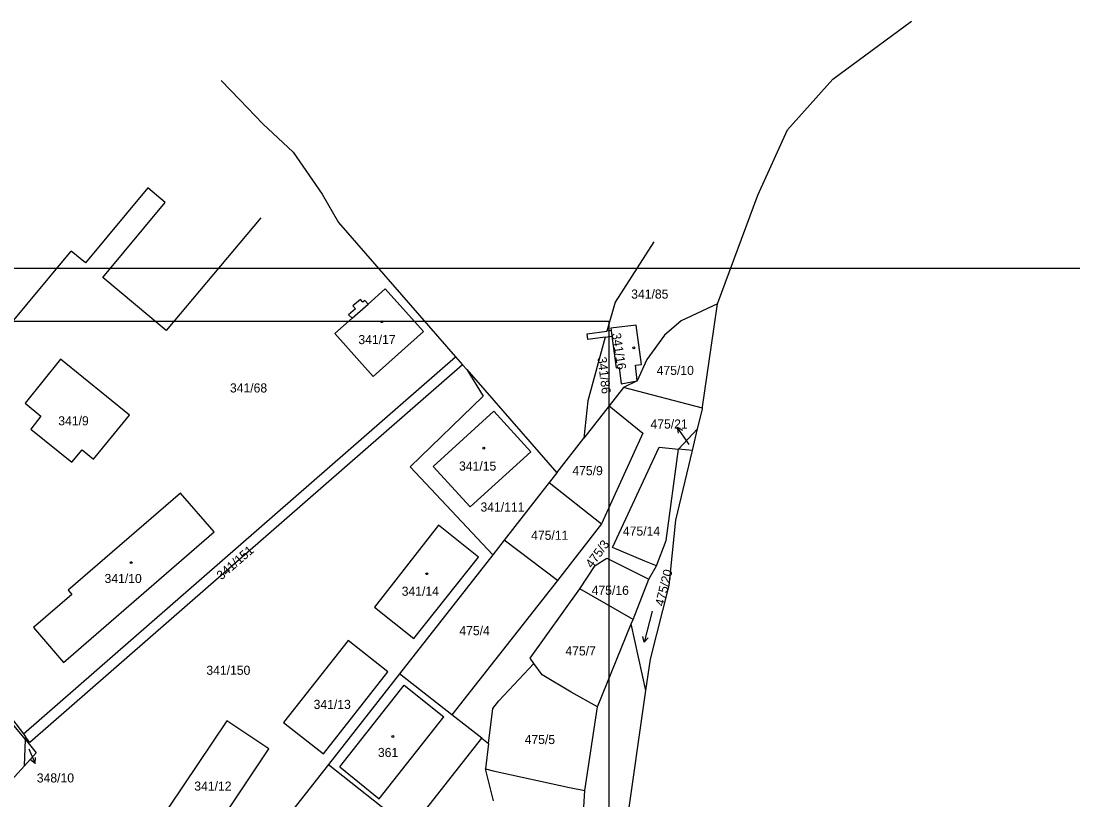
# Model space of a CAD drawing. Extents: x -558500 to -557517, y -1073973 to -1073051.
# Drawn here: x -557909.9 to -557713.2, y -1073289.5 to -1073143.9 of the extents above; entities that cross this region are included whole.
import ezdxf

# ---------------------------------------------------------------- set-up
doc = ezdxf.new("R2010")
doc.units = 0
for name, color, linetype in [('Default', 7, 'Continuous'), ('Hranice parcel', 7, 'Continuous'), ('Parcelní čísla', 7, 'Continuous'), ('Pop  PČ popisy', 7, 'Continuous'), ('Vnitřní kresba', 7, 'Continuous'), ('Vrstva 1', 7, 'Continuous'), ('Značky budov', 7, 'Continuous'), ('Značky kultur', 7, 'Continuous')]:
    doc.layers.add(name, color=color, linetype=linetype)

msp = doc.modelspace()

# ---------------------------------------------------------------- linework, layer by layer
at = {"layer": 'Default'}
msp.add_lwpolyline([(-557909.21, -1073700), (-558500, -1073700), (-558500, -1073200), (-557800, -1073200), (-557800, -1073567.6)], dxfattribs=at)
at = {"layer": 'Hranice parcel'}
for p, q in [((-557780.35, -1073201.52), (-557779.66, -1073196.74)), ((-557782.46, -1073216.02), (-557780.35, -1073201.52)), ((-557909.46, -1073277.19), (-557828.67, -1073206.65)), ((-557828.67, -1073206.65), (-557827.35, -1073208.16)), ((-557827.35, -1073208.16), (-557826.56, -1073209.07)), ((-557826.56, -1073209.07), (-557809.74, -1073228.36)), ((-557794.69, -1073211.15), (-557797.26, -1073212.4)), ((-557797.26, -1073212.4), (-557799.96, -1073215.86)), ((-557782.49, -1073216.26), (-557797.26, -1073212.4)), ((-557799.96, -1073215.86), (-557804.68, -1073221.89)), ((-557782.49, -1073216.26), (-557782.46, -1073216.02)), ((-557786.97, -1073223.95), (-557783.4, -1073220.15)), ((-557784.37, -1073224.22), (-557783.4, -1073220.15)), ((-557809.74, -1073228.36), (-557804.68, -1073221.89)), ((-557784.37, -1073224.22), (-557786.97, -1073223.95)), ((-557809.74, -1073228.36), (-557811.18, -1073230.2)), ((-557811.18, -1073230.2), (-557819.59, -1073240.96)), ((-557811.18, -1073230.2), (-557801.34, -1073237.87)), ((-557801.34, -1073237.87), (-557809.56, -1073248.5)), ((-557819.59, -1073240.96), (-557821.71, -1073243.68)), ((-557809.56, -1073248.5), (-557819.59, -1073240.96)), ((-557821.71, -1073243.68), (-557839.11, -1073265.95)), ((-557792.5, -1073248.24), (-557791.11, -1073245.75)), ((-557795.47, -1073255.77), (-557792.5, -1073248.24)), ((-557795.47, -1073255.77), (-557805.42, -1073250.06)), ((-557909.08, -1073278.25), (-557930.32, -1073252.64)), ((-557795.8, -1073256.6), (-557795.47, -1073255.77)), ((-557802.11, -1073272.13), (-557795.8, -1073256.6)), ((-557793.06, -1073269.04), (-557795.8, -1073256.6)), ((-557839.11, -1073265.95), (-557852.38, -1073282.88)), ((-557829.36, -1073273.59), (-557839.11, -1073265.95)), ((-557796.66, -1073294.23), (-557793.06, -1073269.04)), ((-557804.5, -1073287.75), (-557802.11, -1073272.13)), ((-557823.76, -1073277.98), (-557829.36, -1073273.59)), ((-557909.46, -1073277.19), (-557909.06, -1073277.71)), ((-557909.06, -1073277.71), (-557909.08, -1073278.25)), ((-557837.1, -1073294.96), (-557823.76, -1073277.98)), ((-557823.76, -1073277.98), (-557822.5, -1073278.97)), ((-557909.23, -1073283.14), (-557909.08, -1073278.25)), ((-557822.5, -1073278.97), (-557823.08, -1073283.72)), ((-557912.91, -1073287.22), (-557909.23, -1073283.14)), ((-557852.38, -1073282.88), (-557892.99, -1073334.25)), ((-557852.38, -1073282.88), (-557837.1, -1073294.96)), ((-557821.55, -1073289.72), (-557823.08, -1073283.72)), ((-557805.19, -1073300.2), (-557804.5, -1073287.75))]:
    msp.add_line(p, q, dxfattribs=at)
for points in [[(-557779.66, -1073196.74), (-557772.11, -1073176.43), (-557766.56, -1073164.21), (-557758.13, -1073154.77), (-557743.42, -1073143.89)], [(-557872.45, -1073154.98), (-557868.98, -1073158.62), (-557864.71, -1073163.09), (-557859, -1073168.41), (-557853.62, -1073176.23), (-557850.51, -1073181.56), (-557828.67, -1073206.65)], [(-557886.21, -1073175.05), (-557897.85, -1073189.08), (-557900.5, -1073186.91)], [(-557865.08, -1073180.66), (-557882.73, -1073201.74), (-557894.59, -1073191.83), (-557882.93, -1073177.84), (-557886.21, -1073175.05)], [(-557933.22, -1073178.38), (-557938.16, -1073184.28), (-557924.03, -1073196.06), (-557926.52, -1073199.04), (-557917.14, -1073206.89), (-557900.5, -1073186.91)], [(-557791.57, -1073185.2), (-557798.84, -1073196.43), (-557800.39, -1073201.86)], [(-557845.64, -1073196.14), (-557845.97, -1073196.44), (-557846.43, -1073195.93), (-557847.88, -1073197.13), (-557847.39, -1073197.71), (-557848.66, -1073198.84), (-557848, -1073199.43), (-557851.22, -1073202.29), (-557844.06, -1073210.35), (-557834.66, -1073201.96), (-557841.8, -1073193.95), (-557845.02, -1073196.82), (-557845.64, -1073196.14)], [(-557779.66, -1073196.74), (-557786.44, -1073199.97), (-557789.57, -1073202.65), (-557792.87, -1073207.17), (-557794.69, -1073211.15)], [(-557794.69, -1073211.15), (-557795, -1073208.24), (-557793.89, -1073208.1), (-557794.86, -1073200.76), (-557799.62, -1073201.3), (-557799.56, -1073201.75), (-557800.39, -1073201.86)], [(-557800.69, -1073202.99), (-557803.91, -1073214.91), (-557804.68, -1073221.89)], [(-557800.69, -1073202.99), (-557803.9, -1073203.42), (-557804.04, -1073202.35), (-557800.39, -1073201.86)], [(-557800.69, -1073202.99), (-557799.42, -1073202.82), (-557798.62, -1073208.73), (-557798.08, -1073208.66), (-557797.7, -1073211.74), (-557794.69, -1073211.15)], [(-557906.17, -1073217.76), (-557908.09, -1073220.19), (-557900.4, -1073226.4), (-557898.47, -1073224.04), (-557896.35, -1073225.84), (-557889.61, -1073217.61), (-557902.52, -1073207.11), (-557909.1, -1073215.34), (-557906.17, -1073217.76)], [(-557827.35, -1073208.16), (-557908.24, -1073278.78), (-557909.06, -1073277.71)], [(-557826.56, -1073209.07), (-557823.48, -1073214.05), (-557837.12, -1073227.22), (-557821.71, -1073243.68)], [(-557821.48, -1073216.83), (-557832.85, -1073227.17), (-557825.95, -1073234.71), (-557814.6, -1073224.41), (-557821.48, -1073216.83)], [(-557799.96, -1073215.86), (-557793.64, -1073220.96), (-557801.34, -1073237.87)], [(-557783.4, -1073220.15), (-557782.51, -1073216.43), (-557782.49, -1073216.26)], [(-557791.11, -1073245.75), (-557793.29, -1073244.89), (-557799.3, -1073242.34), (-557790.59, -1073223.57), (-557786.97, -1073223.95)], [(-557793.06, -1073269.04), (-557792.22, -1073263.19), (-557788.74, -1073249.45), (-557787.48, -1073237.23), (-557784.37, -1073224.22)], [(-557791.11, -1073245.75), (-557789.25, -1073241.02), (-557786.97, -1073223.95)], [(-557900.41, -1073251.11), (-557907.58, -1073257.29), (-557901.97, -1073263.84), (-557873.78, -1073239.42), (-557880.11, -1073232.15), (-557901.06, -1073250.32), (-557900.41, -1073251.11)], [(-557824.39, -1073244.13), (-557831.84, -1073238.15), (-557843.81, -1073253.48), (-557836.43, -1073259.33), (-557824.39, -1073244.13)], [(-557805.42, -1073250.06), (-557802.52, -1073245.72), (-557800.36, -1073244.34), (-557792.5, -1073248.24)], [(-557809.56, -1073248.5), (-557824.33, -1073267.21), (-557829.36, -1073273.59)], [(-557930.24, -1073250.53), (-557916.49, -1073268.06), (-557909.46, -1073277.19)], [(-557814, -1073264.03), (-557814.7, -1073263), (-557805.42, -1073250.06)], [(-557841.31, -1073265.58), (-557848.76, -1073259.71), (-557860.82, -1073275.02), (-557853.36, -1073280.89), (-557841.31, -1073265.58)], [(-557822.5, -1073278.97), (-557821.7, -1073272.42), (-557820.57, -1073271), (-557814, -1073264.03)], [(-557802.11, -1073272.13), (-557807.06, -1073269.39), (-557812.44, -1073266.12), (-557814, -1073264.03)], [(-557863.55, -1073279.98), (-557871.4, -1073274.72), (-557882.24, -1073290.87), (-557874.41, -1073296.22), (-557863.55, -1073279.98)], [(-557909.08, -1073278.25), (-557907.04, -1073280.71), (-557909.23, -1073283.14)], [(-557823.08, -1073283.72), (-557821.62, -1073284.11), (-557807.33, -1073287.22), (-557804.5, -1073287.75)]]:
    msp.add_lwpolyline(points, dxfattribs=at)
at = {"layer": 'Pop  PČ popisy'}
for p, q in [((-557785.49, -1073222.3), (-557787.21, -1073219.84)), ((-557787.21, -1073219.84), (-557786.23, -1073220.38)), ((-557787.21, -1073219.84), (-557787.05, -1073220.95)), ((-557784.97, -1073223.04), (-557785.49, -1073222.3)), ((-557908.42, -1073279.97), (-557907.25, -1073282.73)), ((-557907.25, -1073282.73), (-557908.1, -1073282.01)), ((-557907.25, -1073282.73), (-557907.18, -1073281.61))]:
    msp.add_line(p, q, dxfattribs=at)
at = {"layer": 'Vnitřní kresba'}
for p, q in [((-557848, -1073199.43), (-557845.02, -1073196.82)), ((-557799.56, -1073201.75), (-557799.42, -1073202.82)), ((-557850.28, -1073283.35), (-557838.25, -1073268.06)), ((-557838.25, -1073268.06), (-557830.86, -1073274.01)), ((-557842.92, -1073289.34), (-557830.86, -1073274.01)), ((-557850.28, -1073283.35), (-557842.92, -1073289.34))]:
    msp.add_line(p, q, dxfattribs=at)
at = {"layer": 'Vrstva 1'}
msp.add_line((-558357.53, -1073190.09), (-557516.53, -1073190.09), dxfattribs=at)
at = {"layer": 'Značky budov'}
for centre in [(-557842.41, -1073200.11), (-557795.31, -1073205.01), (-557823.39, -1073223.75), (-557889.3, -1073245.15), (-557834.01, -1073247.22), (-557840.37, -1073277.65)]:
    msp.add_circle(centre, 0.175, dxfattribs=at)
at = {"layer": 'Značky kultur'}
for p, q in [((-557791.86, -1073254.23), (-557793.41, -1073260.02)), ((-557793.41, -1073260.02), (-557793.64, -1073258.95)), ((-557793.41, -1073260.02), (-557792.67, -1073259.21))]:
    msp.add_line(p, q, dxfattribs=at)

# ---------------------------------------------------------------- texts
at = {"layer": 'Parcelní čísla'}
for s, p in [('341/85', (-557795.81, -1073195.79)), ('341/17', (-557846.82, -1073204.3)), ('475/10', (-557791.05, -1073210.06)), ('341/68', (-557870.83, -1073213.34)), ('341/9', (-557902.93, -1073219.49)), ('475/21', (-557792.2, -1073220.09)), ('341/15', (-557828, -1073227.95)), ('475/9', (-557806.81, -1073228.81)), ('341/111', (-557823.99, -1073235.61)), ('475/14', (-557797.36, -1073240.1)), ('475/11', (-557814.52, -1073240.89)), ('341/10', (-557894.28, -1073248.97)), ('341/14', (-557838.72, -1073251.35)), ('475/16', (-557803.2, -1073251.18)), ('475/4', (-557827.94, -1073258.73)), ('475/7', (-557808.11, -1073262.51)), ('341/150', (-557875.24, -1073266.13)), ('341/13', (-557855.19, -1073272.51)), ('475/5', (-557815.73, -1073279.08)), ('361', (-557843.17, -1073281.5)), ('348/10', (-557906.94, -1073286.26)), ('341/12', (-557877.5, -1073287.79))]:
    msp.add_text(s, height=1.7, dxfattribs=at).set_placement(p)
for s, rotation, p in [('341/16', 279, (-557799.46, -1073202.33)), ('341/86', 277, (-557802.12, -1073206.77)), ('341/151', 41, (-557872.43, -1073248.49)), ('475/3', 54, (-557803.13, -1073246.32)), ('475/20', 76, (-557789.74, -1073253.41))]:
    msp.add_text(s, height=1.7, rotation=rotation, dxfattribs=at).set_placement(p)

doc.saveas('drawing.dxf')
